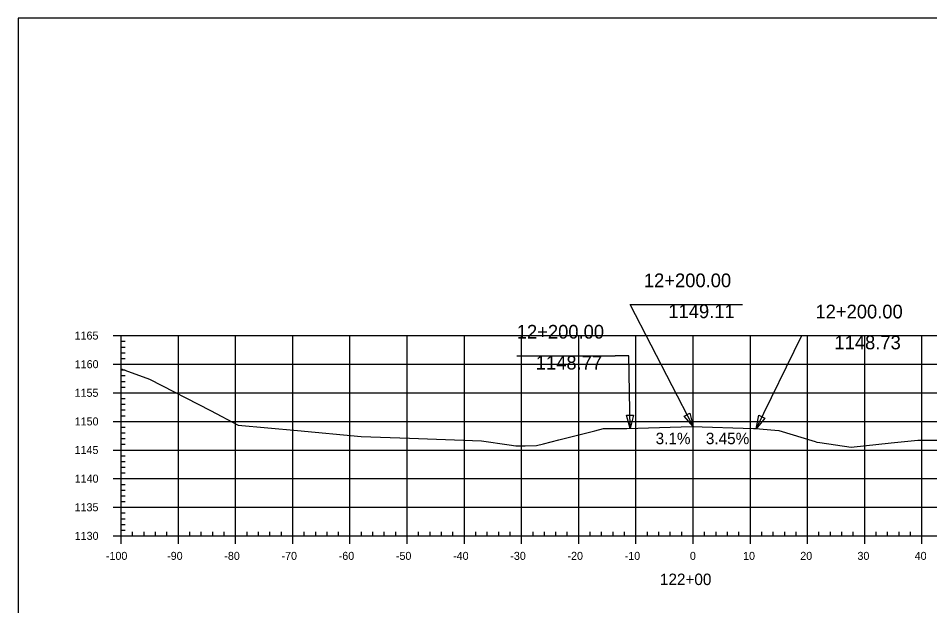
# Model space of a CAD drawing. Extents: x 688474 to 694748, y 765018 to 767373.
# Drawn here: x 690038.3 to 690197.7, y 765401.1 to 765503.8 of the extents above; entities that cross this region are included whole.
import ezdxf

# ---------------------------------------------------------------- set-up
doc = ezdxf.new("R2010")
doc.units = 0
for name, color, linetype in [('60', 7, 'Continuous'), ('Default', 7, 'Continuous'), ('R_Exist Surface', 7, 'Continuous'), ('R_Grid', 7, 'Continuous'), ('R_No Plot', 7, 'Continuous'), ('R_Xsect Slope', 7, 'Continuous')]:
    doc.layers.add(name, color=color, linetype=linetype)

msp = doc.modelspace()

# ---------------------------------------------------------------- linework, layer by layer
at = {"layer": '60'}
for p, q in [((690054.91, 765448.32), (690057.71, 765448.32)), ((690056.31, 765413.32), (690056.31, 765448.32)), ((690056.31, 765447.32), (690057.01, 765447.32)), ((690056.31, 765446.32), (690057.01, 765446.32)), ((690056.31, 765445.32), (690057.01, 765445.32)), ((690056.31, 765444.32), (690057.01, 765444.32)), ((690054.91, 765443.32), (690057.71, 765443.32)), ((690056.31, 765442.32), (690057.01, 765442.32)), ((690056.31, 765441.32), (690057.01, 765441.32)), ((690056.31, 765440.32), (690057.01, 765440.32)), ((690054.91, 765438.32), (690057.71, 765438.32)), ((690056.31, 765439.32), (690057.01, 765439.32)), ((690056.31, 765437.32), (690057.01, 765437.32)), ((690056.31, 765436.32), (690057.01, 765436.32)), ((690056.31, 765435.32), (690057.01, 765435.32)), ((690054.91, 765433.32), (690057.71, 765433.32)), ((690056.31, 765434.32), (690057.01, 765434.32)), ((690056.31, 765432.32), (690057.01, 765432.32)), ((690056.31, 765431.32), (690057.01, 765431.32)), ((690056.31, 765430.32), (690057.01, 765430.32)), ((690054.91, 765428.32), (690057.71, 765428.32)), ((690056.31, 765429.32), (690057.01, 765429.32)), ((690056.31, 765427.32), (690057.01, 765427.32)), ((690056.31, 765426.32), (690057.01, 765426.32)), ((690056.31, 765425.32), (690057.01, 765425.32)), ((690056.31, 765424.32), (690057.01, 765424.32)), ((690054.91, 765423.32), (690057.71, 765423.32)), ((690056.31, 765422.32), (690057.01, 765422.32)), ((690056.31, 765421.32), (690057.01, 765421.32)), ((690056.31, 765420.32), (690057.01, 765420.32)), ((690056.31, 765419.32), (690057.01, 765419.32)), ((690054.91, 765418.32), (690057.71, 765418.32)), ((690056.31, 765417.32), (690057.01, 765417.32)), ((690056.31, 765416.32), (690057.01, 765416.32)), ((690056.31, 765415.32), (690057.01, 765415.32)), ((690056.31, 765411.92), (690056.31, 765414.72)), ((690056.31, 765414.32), (690057.01, 765414.32)), ((690058.31, 765413.32), (690058.31, 765414.02)), ((690060.31, 765413.32), (690060.31, 765414.02)), ((690062.31, 765413.32), (690062.31, 765414.02)), ((690064.31, 765413.32), (690064.31, 765414.02)), ((690066.31, 765411.92), (690066.31, 765414.72)), ((690068.31, 765413.32), (690068.31, 765414.02)), ((690070.31, 765413.32), (690070.31, 765414.02)), ((690072.31, 765413.32), (690072.31, 765414.02)), ((690074.31, 765413.32), (690074.31, 765414.02)), ((690076.31, 765411.92), (690076.31, 765414.72)), ((690078.31, 765413.32), (690078.31, 765414.02)), ((690080.31, 765413.32), (690080.31, 765414.02)), ((690082.31, 765413.32), (690082.31, 765414.02)), ((690084.31, 765413.32), (690084.31, 765414.02)), ((690086.31, 765411.92), (690086.31, 765414.72)), ((690088.31, 765413.32), (690088.31, 765414.02)), ((690090.31, 765413.32), (690090.31, 765414.02)), ((690092.31, 765413.32), (690092.31, 765414.02)), ((690094.31, 765413.32), (690094.31, 765414.02)), ((690096.31, 765411.92), (690096.31, 765414.72)), ((690098.31, 765413.32), (690098.31, 765414.02)), ((690100.31, 765413.32), (690100.31, 765414.02)), ((690102.31, 765413.32), (690102.31, 765414.02)), ((690104.31, 765413.32), (690104.31, 765414.02)), ((690106.31, 765411.92), (690106.31, 765414.72)), ((690108.31, 765413.32), (690108.31, 765414.02)), ((690110.31, 765413.32), (690110.31, 765414.02)), ((690112.31, 765413.32), (690112.31, 765414.02)), ((690114.31, 765413.32), (690114.31, 765414.02)), ((690116.31, 765411.92), (690116.31, 765414.72)), ((690118.31, 765413.32), (690118.31, 765414.02)), ((690120.31, 765413.32), (690120.31, 765414.02)), ((690122.31, 765413.32), (690122.31, 765414.02)), ((690124.31, 765413.32), (690124.31, 765414.02)), ((690126.31, 765411.92), (690126.31, 765414.72)), ((690128.31, 765413.32), (690128.31, 765414.02)), ((690130.31, 765413.32), (690130.31, 765414.02)), ((690132.31, 765413.32), (690132.31, 765414.02)), ((690134.31, 765413.32), (690134.31, 765414.02)), ((690136.31, 765411.92), (690136.31, 765414.72)), ((690138.31, 765413.32), (690138.31, 765414.02)), ((690140.31, 765413.32), (690140.31, 765414.02)), ((690142.31, 765413.32), (690142.31, 765414.02)), ((690144.31, 765413.32), (690144.31, 765414.02)), ((690146.31, 765411.92), (690146.31, 765414.72)), ((690148.31, 765413.32), (690148.31, 765414.02)), ((690150.31, 765413.32), (690150.31, 765414.02)), ((690152.31, 765413.32), (690152.31, 765414.02)), ((690154.31, 765413.32), (690154.31, 765414.02)), ((690156.31, 765411.92), (690156.31, 765414.72)), ((690158.31, 765413.32), (690158.31, 765414.02)), ((690160.31, 765413.32), (690160.31, 765414.02)), ((690162.31, 765413.32), (690162.31, 765414.02)), ((690164.31, 765413.32), (690164.31, 765414.02)), ((690166.31, 765411.92), (690166.31, 765414.72)), ((690168.31, 765413.32), (690168.31, 765414.02)), ((690170.31, 765413.32), (690170.31, 765414.02)), ((690172.31, 765413.32), (690172.31, 765414.02)), ((690174.31, 765413.32), (690174.31, 765414.02)), ((690176.31, 765411.92), (690176.31, 765414.72)), ((690178.31, 765413.32), (690178.31, 765414.02)), ((690180.31, 765413.32), (690180.31, 765414.02)), ((690182.31, 765413.32), (690182.31, 765414.02)), ((690184.31, 765413.32), (690184.31, 765414.02)), ((690186.31, 765411.92), (690186.31, 765414.72)), ((690188.31, 765413.32), (690188.31, 765414.02)), ((690190.31, 765413.32), (690190.31, 765414.02)), ((690192.31, 765413.32), (690192.31, 765414.02)), ((690194.31, 765413.32), (690194.31, 765414.02)), ((690196.31, 765411.92), (690196.31, 765414.72)), ((690054.91, 765413.32), (690057.71, 765413.32)), ((690056.31, 765413.32), (690256.31, 765413.32))]:
    msp.add_line(p, q, dxfattribs=at)
at = {"layer": 'R_Exist Surface'}
for p, q in [((690147.69, 765453.77), (690164.92, 765453.77)), ((690177.69, 765448.32), (690194.92, 765448.32)), ((690125.47, 765444.79), (690142.69, 765444.79))]:
    msp.add_line(p, q, dxfattribs=at)
for points in [[(690156.31, 765432.43), (690145.29, 765453.77), (690147.69, 765453.77)], [(690167.31, 765432.05), (690175.29, 765448.32), (690177.69, 765448.32)], [(690145.31, 765432.1), (690145.09, 765444.79), (690142.69, 765444.79)], [(690056.31, 765442.52), (690061.24, 765440.7), (690071.94, 765435.23), (690076.76, 765432.66), (690087.14, 765431.73), (690098.26, 765430.67), (690106.73, 765430.37), (690119.29, 765429.94), (690124.12, 765429.24), (690125.3, 765429.06), (690126.96, 765429.08), (690128.91, 765429.13), (690130.13, 765429.4), (690132.84, 765430.09), (690139.1, 765431.68), (690140.63, 765432.07), (690141.1, 765432.07), (690144.52, 765432.08), (690144.73, 765432.08), (690146.61, 765432.14), (690156.1, 765432.42), (690166.86, 765432.07), (690167.22, 765432.06), (690170.58, 765431.8), (690171.31, 765431.75), (690177.65, 765429.79), (690177.94, 765429.71), (690178.45, 765429.63), (690183.93, 765428.81), (690190.94, 765429.59), (690195.61, 765430.04), (690199.33, 765430.07)]]:
    msp.add_lwpolyline(points, dxfattribs=at)
for points in [[(690156.31, 765432.43), (690154.72, 765434.23), (690155.75, 765434.77)], [(690145.31, 765432.1), (690144.68, 765434.42), (690145.85, 765434.44)], [(690167.31, 765432.05), (690167.81, 765434.4), (690168.85, 765433.88)]]:
    msp.add_lwpolyline(points, close=True, dxfattribs=at)
at = {"layer": 'R_Grid'}
for p, q in [((690056.31, 765448.32), (690256.31, 765448.32)), ((690056.31, 765413.32), (690056.31, 765448.32)), ((690066.31, 765413.32), (690066.31, 765448.32)), ((690076.31, 765413.32), (690076.31, 765448.32)), ((690086.31, 765413.32), (690086.31, 765448.32)), ((690096.31, 765413.32), (690096.31, 765448.32)), ((690106.31, 765413.32), (690106.31, 765448.32)), ((690116.31, 765413.32), (690116.31, 765448.32)), ((690126.31, 765413.32), (690126.31, 765448.32)), ((690136.31, 765413.32), (690136.31, 765448.32)), ((690146.31, 765413.32), (690146.31, 765448.32)), ((690156.31, 765413.32), (690156.31, 765448.32)), ((690166.31, 765413.32), (690166.31, 765448.32)), ((690176.31, 765413.32), (690176.31, 765448.32)), ((690186.31, 765413.32), (690186.31, 765448.32)), ((690196.31, 765413.32), (690196.31, 765448.32)), ((690056.31, 765443.32), (690256.31, 765443.32)), ((690056.31, 765438.32), (690256.31, 765438.32)), ((690056.31, 765433.32), (690256.31, 765433.32)), ((690056.31, 765428.32), (690256.31, 765428.32)), ((690056.31, 765423.32), (690256.31, 765423.32)), ((690056.31, 765418.32), (690256.31, 765418.32)), ((690056.31, 765413.32), (690256.31, 765413.32))]:
    msp.add_line(p, q, dxfattribs=at)
at = {"layer": 'R_No Plot'}
msp.add_lwpolyline([(690038.31, 765298.32), (690354.49, 765298.32), (690354.49, 765503.78), (690038.31, 765503.78)], close=True, dxfattribs=at)

# ---------------------------------------------------------------- texts
at = {"layer": '60'}
for s, height, p in [('1165', 1.4, (690048.16, 765447.62)), ('1160', 1.4, (690048.18, 765442.62)), ('1155', 1.4, (690048.16, 765437.62)), ('1150', 1.4, (690048.18, 765432.62)), ('1145', 1.4, (690048.16, 765427.62)), ('1140', 1.4, (690048.18, 765422.62)), ('1135', 1.4, (690048.16, 765417.62)), ('1130', 1.4, (690048.18, 765412.62)), ('-100', 1.4, (690053.64, 765409.12)), ('-90', 1.4, (690064.34, 765409.12)), ('-80', 1.4, (690074.34, 765409.12)), ('-70', 1.4, (690084.34, 765409.12)), ('-60', 1.4, (690094.34, 765409.12)), ('-50', 1.4, (690104.34, 765409.12)), ('-40', 1.4, (690114.34, 765409.12)), ('-30', 1.4, (690124.34, 765409.12)), ('-20', 1.4, (690134.34, 765409.12)), ('-10', 1.4, (690144.34, 765409.12)), ('0', 1.4, (690155.74, 765409.12)), ('10', 1.4, (690165.04, 765409.12)), ('20', 1.4, (690175.04, 765409.12)), ('30', 1.4, (690185.04, 765409.12)), ('40', 1.4, (690195.04, 765409.12)), ('122+00', 2, (690150.5, 765404.72))]:
    msp.add_text(s, height=height, dxfattribs=at).set_placement(p)
at = {"layer": 'Default'}
for s, p in [('3.1%', (690149.75, 765429.34)), ('3.45%', (690158.53, 765429.34))]:
    msp.add_text(s, height=2, dxfattribs=at).set_placement(p)
at = {"layer": 'R_Xsect Slope'}
for s, p in [('12+200.00', (690147.69, 765456.77)), ('1149.11', (690151.97, 765451.37)), ('12+200.00', (690177.69, 765451.32)), ('12+200.00', (690125.47, 765447.79)), ('1148.73', (690181.01, 765445.92)), ('1148.77', (690128.79, 765442.39))]:
    msp.add_text(s, height=2.4, dxfattribs=at).set_placement(p)

doc.saveas('drawing.dxf')
